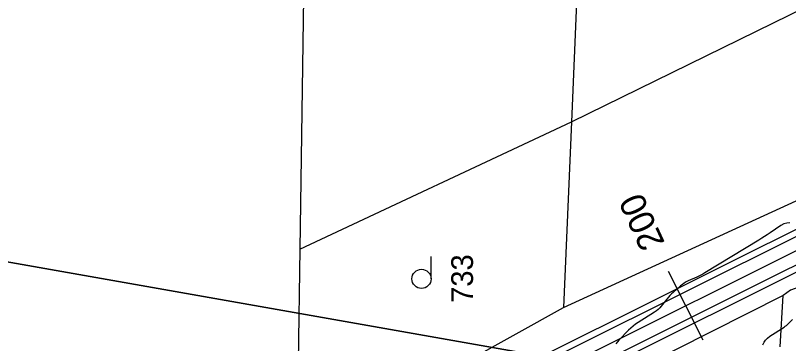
# Model space of a CAD drawing. Extents: x -534481 to -534256, y -1190577 to -1190138.
# Drawn here: x -534395.86 to -534365.66, y -1190356.16 to -1190343.36 of the extents above; entities that cross this region are included whole.
import ezdxf

# ---------------------------------------------------------------- set-up
doc = ezdxf.new("R2010")
doc.units = 0
for name, color, linetype in [('31', 7, 'Continuous'), ('_N_osa', 7, 'Continuous'), ('_N_tenká', 7, 'Continuous'), ('_N_text', 7, 'Continuous'), ('_rámeček', 7, 'Continuous'), ('Hranice parcel', 7, 'Continuous'), ('Parcelní čísla', 7, 'Continuous'), ('Značky kultur', 7, 'Continuous')]:
    doc.layers.add(name, color=color, linetype=linetype)

msp = doc.modelspace()

# ---------------------------------------------------------------- linework, layer by layer
at = {"layer": '31'}
for points in [[(-534365.614, -1190351.448), (-534365.733, -1190351.46), (-534365.848, -1190351.496), (-534365.957, -1190351.556), (-534366.384, -1190351.845), (-534366.492, -1190351.917), (-534366.6, -1190351.987), (-534366.709, -1190352.056), (-534366.818, -1190352.124), (-534368.929, -1190353.411), (-534369.007, -1190353.456), (-534369.086, -1190353.499), (-534369.166, -1190353.539), (-534369.248, -1190353.577), (-534369.578, -1190353.721), (-534369.659, -1190353.761), (-534369.736, -1190353.806), (-534369.809, -1190353.857), (-534369.878, -1190353.913), (-534370.167, -1190354.17), (-534370.232, -1190354.23), (-534370.294, -1190354.293), (-534370.354, -1190354.359), (-534370.411, -1190354.427), (-534370.632, -1190354.705), (-534370.69, -1190354.772), (-534370.753, -1190354.833), (-534370.821, -1190354.889), (-534370.894, -1190354.939), (-534371.538, -1190355.343), (-534371.638, -1190355.41), (-534371.734, -1190355.483), (-534371.825, -1190355.562), (-534371.912, -1190355.646), (-534372.284, -1190356.031), (-534372.349, -1190356.102), (-534372.408, -1190356.177)], [(-534366.664, -1190356.215), (-534366.617, -1190356.115), (-534366.556, -1190356.027), (-534366.481, -1190355.949), (-534366.394, -1190355.882), (-534365.834, -1190355.52), (-534365.79, -1190355.489), (-534365.747, -1190355.456), (-534365.705, -1190355.421), (-534365.666, -1190355.384), (-534365.509, -1190355.229)]]:
    msp.add_lwpolyline(points, dxfattribs=at)
at = {"layer": '_N_osa'}
msp.add_lwpolyline([(-534409.868, -1190391.439), (-534405.947, -1190382.816), (-534400.873, -1190377.487), (-534393.696, -1190372.718), (-534384.927, -1190365.477), (-534382.631, -1190361.148), (-534355.894, -1190347.823), (-534351.738, -1190342.389), (-534351.577, -1190328.316), (-534347.204, -1190300.921), (-534345.553, -1190283.64), (-534344.682, -1190264.494)], dxfattribs=at)
at = {"layer": '_N_tenká'}
for points in [[(-534409.916, -1190390.337), (-534406.368, -1190382.532), (-534401.196, -1190377.102), (-534393.995, -1190372.316), (-534385.322, -1190365.155), (-534382.997, -1190360.772), (-534356.221, -1190347.427), (-534352.236, -1190342.217), (-534352.076, -1190328.274), (-534347.7, -1190300.857), (-534346.052, -1190283.605), (-534345.255, -1190266.096)], [(-534409.879, -1190389.652), (-534406.578, -1190382.39), (-534401.358, -1190376.909), (-534394.144, -1190372.115), (-534385.52, -1190364.994), (-534383.181, -1190360.584), (-534356.384, -1190347.229), (-534352.485, -1190342.131), (-534352.326, -1190328.253), (-534347.948, -1190300.826), (-534346.301, -1190283.588), (-534345.507, -1190266.125)], [(-534409.363, -1190391.537), (-534405.527, -1190383.099), (-534400.549, -1190377.873), (-534393.398, -1190373.12), (-534384.532, -1190365.799), (-534382.264, -1190361.524), (-534355.568, -1190348.219), (-534351.24, -1190342.56), (-534351.077, -1190328.359), (-534346.708, -1190300.984), (-534345.054, -1190283.675), (-534344.256, -1190266.142)], [(-534409.111, -1190391.586), (-534405.317, -1190383.241), (-534400.388, -1190378.065), (-534393.249, -1190373.321), (-534384.335, -1190365.96), (-534382.081, -1190361.712), (-534355.404, -1190348.417), (-534350.991, -1190342.646), (-534350.828, -1190328.38), (-534346.46, -1190301.016), (-534344.805, -1190283.693), (-534344.008, -1190266.196)]]:
    msp.add_lwpolyline(points, dxfattribs=at)
at = {"layer": '_N_text'}
msp.add_lwpolyline([(-534368.997, -1190356.029), (-534370.357, -1190353.355)], dxfattribs=at)
at = {"layer": '_rámeček'}
for points in [[(-534333.072, -1190257.49), (-534426.145, -1190241.079), (-534444.378, -1190344.484), (-534298.134, -1190370.27)], [(-534298.134, -1190370.27), (-534444.378, -1190344.484), (-534462.611, -1190447.888), (-534316.367, -1190473.675)]]:
    msp.add_lwpolyline(points, dxfattribs=at)
at = {"layer": 'Hranice parcel'}
for p, q in [((-534374.14, -1190347.51), (-534353.4, -1190337.34)), ((-534384.58, -1190340.88), (-534384.75, -1190352.48)), ((-534384.75, -1190352.48), (-534374.14, -1190347.51)), ((-534374.14, -1190347.51), (-534374.45, -1190354.76)), ((-534384.75, -1190352.48), (-534384.87, -1190360.53)), ((-534365.99, -1190356.3), (-534365.87, -1190354.29)), ((-534384.87, -1190360.53), (-534374.45, -1190354.76))]:
    msp.add_line(p, q, dxfattribs=at)
for points in [[(-534371.05, -1190311.86), (-534373.6, -1190334.76), (-534374.14, -1190347.51)], [(-534374.45, -1190354.76), (-534357.22, -1190346.86), (-534354.46, -1190343.91)], [(-534355.88, -1190351.91), (-534359.93, -1190352.28), (-534360.78, -1190352.36), (-534365.58, -1190354.08), (-534365.87, -1190354.29)], [(-534365.87, -1190354.29), (-534375.68, -1190359.24), (-534377.88, -1190360.32)]]:
    msp.add_lwpolyline(points, dxfattribs=at)
at = {"layer": 'Značky kultur'}
msp.add_line((-534379.623, -1190353.64), (-534379.623, -1190352.765), dxfattribs=at)
msp.add_circle((-534379.998, -1190353.64), 0.375, dxfattribs=at)

# ---------------------------------------------------------------- texts
at = {"layer": '_N_text'}
msp.add_text('200', height=1, rotation=114.8028, dxfattribs=at).set_placement((-534370.479, -1190352.234))
at = {"layer": 'Parcelní čísla'}
msp.add_text('733', height=0.85, rotation=90, dxfattribs=at).set_placement((-534377.986, -1190354.578))

doc.saveas('drawing.dxf')
